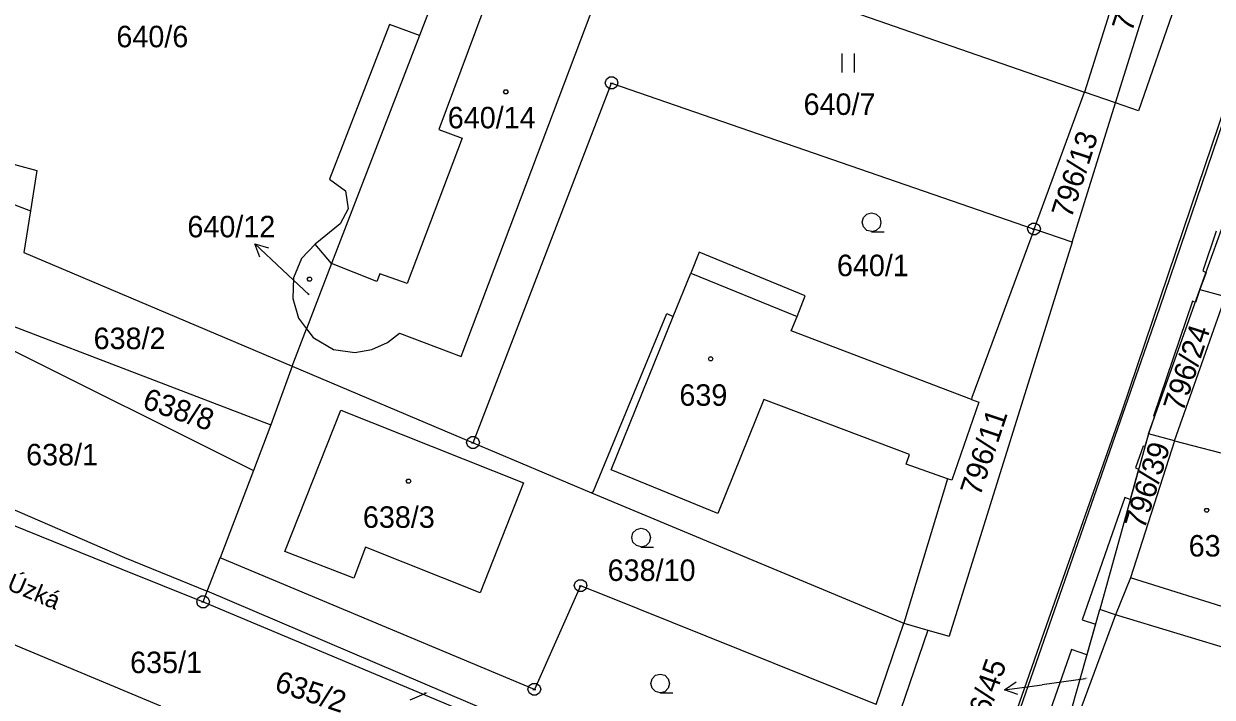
# Model space of a CAD drawing. Extents: x -759060 to -757386, y -1172273 to -1170948.
# Drawn here: x -758101.6 to -758007.6, y -1171349.3 to -1171296.1 of the extents above; entities that cross this region are included whole.
import ezdxf

# ---------------------------------------------------------------- set-up
doc = ezdxf.new("R2010")
doc.units = 0
for name, color, linetype in [('Vrstva 1', 7, 'Continuous'), ('Vrstva 12', 7, 'Continuous'), ('Vrstva 13', 7, 'Continuous'), ('Vrstva 2', 7, 'Continuous'), ('Vrstva 3', 7, 'Continuous'), ('Vrstva 4', 7, 'Continuous'), ('Vrstva 5', 7, 'Continuous'), ('Vrstva 7', 7, 'Continuous'), ('Vrstva 8', 7, 'Continuous')]:
    doc.layers.add(name, color=color, linetype=linetype)

msp = doc.modelspace()

# ---------------------------------------------------------------- linework, layer by layer
at = {"layer": 'Vrstva 1'}
for p, q in [((-758015.23, -1171302.33), (-758009.67, -1171284.51)), ((-758053.7, -1171288.99), (-758017.68, -1171301.49)), ((-758068.26, -1171291.73), (-758070.29, -1171297.01)), ((-758066.98, -1171322.4), (-758055.84, -1171292.86)), ((-758015.58, -1171294.8), (-758017.68, -1171301.49)), ((-758010.54, -1171294.68), (-758013.41, -1171302.97)), ((-758072.67, -1171296.15), (-758077.4, -1171308.38)), ((-758070.29, -1171297.01), (-758072.67, -1171296.15)), ((-758070.29, -1171297.01), (-758077.24, -1171315.05)), ((-758005.04, -1171298.81), (-758011.77, -1171318.56)), ((-758066.05, -1171329.21), (-758055.09, -1171300.77)), ((-758055.09, -1171300.77), (-758021.68, -1171312.32)), ((-758021.68, -1171312.32), (-758017.68, -1171301.49)), ((-758015.23, -1171302.33), (-758017.68, -1171301.49)), ((-758018.67, -1171313.36), (-758015.23, -1171302.33)), ((-758013.41, -1171302.97), (-758015.23, -1171302.33)), ((-758115.76, -1171303.61), (-758100.54, -1171307.69)), ((-758118.62, -1171304.17), (-758101.05, -1171310.87)), ((-758100.54, -1171307.69), (-758101.05, -1171310.87)), ((-758077.4, -1171308.38), (-758076.15, -1171309.28)), ((-758076.15, -1171309.28), (-758075.92, -1171310.72)), ((-758008.56, -1171317.1), (-758006.18, -1171310.44)), ((-758101.05, -1171310.87), (-758101.57, -1171314.17)), ((-758075.92, -1171310.72), (-758076.56, -1171311.89)), ((-758076.56, -1171311.89), (-758078.53, -1171313.5)), ((-758021.68, -1171312.32), (-758026.59, -1171325.64)), ((-758018.67, -1171313.36), (-758021.68, -1171312.32)), ((-758101.57, -1171314.17), (-758080.36, -1171323.15)), ((-758078.53, -1171313.5), (-758079.63, -1171314.63)), ((-758048.16, -1171314.15), (-758048.82, -1171315.79)), ((-758039.77, -1171317.6), (-758048.16, -1171314.15)), ((-758018.67, -1171313.36), (-758028.39, -1171344.5)), ((-758079.63, -1171314.63), (-758080.25, -1171316.18)), ((-758077.24, -1171315.05), (-758079.22, -1171320.2)), ((-758050.21, -1171319.22), (-758048.82, -1171315.79)), ((-758080.25, -1171316.18), (-758080.3, -1171317.81)), ((-758080.3, -1171317.81), (-758079.86, -1171319.36)), ((-758040.42, -1171319.22), (-758039.77, -1171317.6)), ((-758012.64, -1171328.52), (-758008.56, -1171317.1)), ((-758010.57, -1171329.06), (-758006.53, -1171317.65)), ((-758008.56, -1171317.1), (-758006.53, -1171317.65)), ((-758011.77, -1171318.56), (-758028.48, -1171366.58)), ((-758102.97, -1171319.79), (-758082.04, -1171327.79)), ((-758079.86, -1171319.36), (-758079.22, -1171320.2)), ((-758056.53, -1171333.03), (-758050.73, -1171319)), ((-758050.73, -1171319), (-758050.21, -1171319.22)), ((-758040.88, -1171320.35), (-758040.42, -1171319.22)), ((-758080.36, -1171323.15), (-758079.22, -1171320.2)), ((-758079.22, -1171320.2), (-758078.69, -1171320.9)), ((-758072.83, -1171321.29), (-758071.87, -1171320.56)), ((-758071.87, -1171320.56), (-758066.98, -1171322.4)), ((-758026.63, -1171325.78), (-758040.88, -1171320.35)), ((-758103.62, -1171321.33), (-758083.42, -1171331.4)), ((-758078.69, -1171320.9), (-758077.08, -1171321.83)), ((-758074.05, -1171321.85), (-758072.83, -1171321.29)), ((-758077.08, -1171321.83), (-758075.4, -1171322.08)), ((-758075.4, -1171322.08), (-758074.05, -1171321.85)), ((-758080.36, -1171323.15), (-758082.04, -1171327.79)), ((-758080.36, -1171323.15), (-758066.05, -1171329.21)), ((-758124.28, -1171325.01), (-758093.63, -1171338.29)), ((-758026.05, -1171326), (-758028.18, -1171332.18)), ((-758026.59, -1171325.64), (-758026.63, -1171325.78)), ((-758026.63, -1171325.78), (-758026.05, -1171326)), ((-758123.07, -1171327.4), (-758093.82, -1171339.21)), ((-758080.93, -1171337.82), (-758076.5, -1171326.63)), ((-758076.5, -1171326.63), (-758062.06, -1171332.38)), ((-758082.04, -1171327.79), (-758083.42, -1171331.4)), ((-758066.05, -1171329.21), (-758056.67, -1171333.18)), ((-758012.64, -1171328.52), (-758016.49, -1171342.4)), ((-758010.57, -1171329.06), (-758014.04, -1171339.89)), ((-758010.57, -1171329.06), (-758012.64, -1171328.52)), ((-758010.57, -1171329.06), (-758000.35, -1171331.74)), ((-758083.42, -1171331.4), (-758086.06, -1171338.31)), ((-758028.53, -1171332.06), (-758031.98, -1171343.48)), ((-758028.18, -1171332.18), (-758028.53, -1171332.06)), ((-758062.06, -1171332.38), (-758065.5, -1171341.07)), ((-758056.67, -1171333.18), (-758056.53, -1171333.03)), ((-758056.67, -1171333.18), (-758031.98, -1171343.48)), ((-758090.74, -1171350.03), (-758125.45, -1171335.56)), ((-758074.57, -1171337.47), (-758075.48, -1171339.92)), ((-758065.5, -1171341.07), (-758074.57, -1171337.47)), ((-758093.63, -1171338.29), (-758087.08, -1171340.96)), ((-758087.08, -1171340.96), (-758086.06, -1171338.31)), ((-758061.2, -1171348.72), (-758086.06, -1171338.31)), ((-758075.48, -1171339.92), (-758080.93, -1171337.82)), ((-758093.82, -1171339.21), (-758087.4, -1171341.8)), ((-758057.54, -1171340.52), (-758061.2, -1171348.72)), ((-758055.68, -1171341.27), (-758057.54, -1171340.52)), ((-758014.04, -1171339.89), (-758015.25, -1171342.81)), ((-758087.4, -1171341.8), (-758087.08, -1171340.96)), ((-758062.42, -1171351.45), (-758087.08, -1171340.96)), ((-758034.18, -1171349.9), (-758055.68, -1171341.27)), ((-758087.4, -1171341.8), (-758056.26, -1171354.83)), ((-758020.68, -1171357.21), (-758016.49, -1171342.4)), ((-758015.25, -1171342.81), (-758016.49, -1171342.4)), ((-758015.25, -1171342.81), (-758018.53, -1171351.67)), ((-758001.93, -1171346.84), (-758015.25, -1171342.81)), ((-758030.08, -1171344.02), (-758040.94, -1171375.78)), ((-758034.18, -1171349.9), (-758031.98, -1171343.48)), ((-758031.98, -1171343.48), (-758030.08, -1171344.02)), ((-758030.08, -1171344.02), (-758028.39, -1171344.5))]:
    msp.add_line(p, q, dxfattribs=at)
at = {"layer": 'Vrstva 12'}
for p, q in [((-758066.98, -1171322.4), (-758055.84, -1171292.86)), ((-758065.27, -1171295.12), (-758068.76, -1171304.43)), ((-758068.76, -1171304.43), (-758066.91, -1171305.12)), ((-758066.91, -1171305.12), (-758071.27, -1171316.61)), ((-758078.53, -1171313.5), (-758079.63, -1171314.63)), ((-758077.24, -1171315.05), (-758078.53, -1171313.5)), ((-758079.63, -1171314.63), (-758080.25, -1171316.18)), ((-758073.65, -1171316.46), (-758077.24, -1171315.05)), ((-758073.42, -1171315.85), (-758073.65, -1171316.46)), ((-758071.27, -1171316.61), (-758073.42, -1171315.85)), ((-758050.21, -1171319.22), (-758048.82, -1171315.79)), ((-758048.82, -1171315.79), (-758040.42, -1171319.22)), ((-758080.25, -1171316.18), (-758080.3, -1171317.81)), ((-758080.3, -1171317.81), (-758079.86, -1171319.36)), ((-758010.57, -1171329.06), (-758006.53, -1171317.65)), ((-758079.86, -1171319.36), (-758079.22, -1171320.2)), ((-758055.12, -1171331.36), (-758050.21, -1171319.22)), ((-758040.88, -1171320.35), (-758040.42, -1171319.22)), ((-758079.22, -1171320.2), (-758078.69, -1171320.9)), ((-758072.83, -1171321.29), (-758071.87, -1171320.56)), ((-758071.87, -1171320.56), (-758066.98, -1171322.4)), ((-758026.63, -1171325.78), (-758040.88, -1171320.35)), ((-758078.69, -1171320.9), (-758077.08, -1171321.83)), ((-758074.05, -1171321.85), (-758072.83, -1171321.29)), ((-758077.08, -1171321.83), (-758075.4, -1171322.08)), ((-758075.4, -1171322.08), (-758074.05, -1171321.85)), ((-758043.06, -1171325.78), (-758046.69, -1171334.8)), ((-758031.53, -1171330.15), (-758043.06, -1171325.78)), ((-758026.05, -1171326), (-758028.18, -1171332.18)), ((-758026.63, -1171325.78), (-758026.05, -1171326)), ((-758080.93, -1171337.82), (-758076.5, -1171326.63)), ((-758076.5, -1171326.63), (-758062.06, -1171332.38)), ((-758010.57, -1171329.06), (-758014.04, -1171339.89)), ((-758010.57, -1171329.06), (-758000.35, -1171331.74)), ((-758010.57, -1171329.06), (-758000.35, -1171331.74)), ((-758031.8, -1171330.91), (-758031.53, -1171330.15)), ((-758028.53, -1171332.06), (-758031.8, -1171330.91)), ((-758046.69, -1171334.8), (-758055.12, -1171331.36)), ((-758028.18, -1171332.18), (-758028.53, -1171332.06)), ((-758062.06, -1171332.38), (-758065.5, -1171341.07)), ((-758074.57, -1171337.47), (-758075.48, -1171339.92)), ((-758065.5, -1171341.07), (-758074.57, -1171337.47)), ((-758075.48, -1171339.92), (-758080.93, -1171337.82)), ((-758005.32, -1171342.63), (-758014.04, -1171339.89))]:
    msp.add_line(p, q, dxfattribs=at)
at = {"layer": 'Vrstva 13'}
for p, q in [((-758009.23, -1171310.47), (-758005.04, -1171298.09)), ((-758011.08, -1171315.93), (-758009.23, -1171310.47)), ((-758007.27, -1171312.47), (-758008.34, -1171315.63)), ((-758014.75, -1171326.77), (-758011.08, -1171315.93)), ((-758008.07, -1171315.74), (-758008.56, -1171317.1)), ((-758008.34, -1171315.63), (-758008.07, -1171315.74)), ((-758009.15, -1171318.01), (-758012.23, -1171327.12)), ((-758008.92, -1171318.11), (-758009.15, -1171318.01)), ((-758008.56, -1171317.1), (-758008.92, -1171318.11)), ((-758020.66, -1171343.58), (-758014.75, -1171326.77)), ((-758012.15, -1171327.15), (-758012.64, -1171328.52)), ((-758012.23, -1171327.12), (-758012.15, -1171327.15)), ((-758012.64, -1171328.52), (-758012.92, -1171329.52)), ((-758013.05, -1171329.48), (-758013.66, -1171331.19)), ((-758012.92, -1171329.52), (-758013.05, -1171329.48)), ((-758013.41, -1171331.29), (-758014.08, -1171333.71)), ((-758013.66, -1171331.19), (-758013.41, -1171331.29)), ((-758014.49, -1171333.55), (-758017.88, -1171343.21)), ((-758014.08, -1171333.71), (-758014.49, -1171333.55)), ((-758017.88, -1171343.21), (-758016.82, -1171343.57)), ((-758026.92, -1171361.39), (-758020.66, -1171343.58)), ((-758016.82, -1171343.57), (-758017.5, -1171345.98)), ((-758018.71, -1171345.57), (-758024.12, -1171360.96)), ((-758017.5, -1171345.98), (-758018.71, -1171345.57))]:
    msp.add_line(p, q, dxfattribs=at)
at = {"layer": 'Vrstva 3'}
for p, q in [((-758036.88, -1171298.43), (-758036.88, -1171299.93)), ((-758035.88, -1171299.93), (-758035.88, -1171298.43))]:
    msp.add_line(p, q, dxfattribs=at)
for points in [[(-758034.52, -1171312.52), (-758034.9, -1171312.42), (-758035.17, -1171312.15), (-758035.27, -1171311.78), (-758035.17, -1171311.41), (-758034.9, -1171311.14), (-758034.53, -1171311.04), (-758034.16, -1171311.14), (-758033.89, -1171311.41), (-758033.79, -1171311.79), (-758033.89, -1171312.17), (-758034.16, -1171312.44), (-758034.54, -1171312.54), (-758033.54, -1171312.54)], [(-758052.75, -1171337.44), (-758053.13, -1171337.34), (-758053.4, -1171337.07), (-758053.5, -1171336.7), (-758053.4, -1171336.33), (-758053.13, -1171336.06), (-758052.76, -1171335.96), (-758052.39, -1171336.06), (-758052.12, -1171336.33), (-758052.02, -1171336.71), (-758052.12, -1171337.09), (-758052.39, -1171337.36), (-758052.77, -1171337.46), (-758051.77, -1171337.46)], [(-758051.24, -1171348.98), (-758051.62, -1171348.88), (-758051.89, -1171348.61), (-758051.99, -1171348.24), (-758051.89, -1171347.87), (-758051.62, -1171347.6), (-758051.25, -1171347.5), (-758050.88, -1171347.6), (-758050.61, -1171347.87), (-758050.51, -1171348.25), (-758050.61, -1171348.63), (-758050.88, -1171348.9), (-758051.26, -1171349), (-758050.26, -1171349)]]:
    msp.add_lwpolyline(points, dxfattribs=at)
at = {"layer": 'Vrstva 4'}
for p, q in [((-758065.27, -1171295.12), (-758068.76, -1171304.43)), ((-758068.76, -1171304.43), (-758066.91, -1171305.12)), ((-758066.91, -1171305.12), (-758071.27, -1171316.61)), ((-758077.24, -1171315.05), (-758078.53, -1171313.5)), ((-758073.65, -1171316.46), (-758077.24, -1171315.05)), ((-758073.42, -1171315.85), (-758073.65, -1171316.46)), ((-758071.27, -1171316.61), (-758073.42, -1171315.85)), ((-758048.82, -1171315.79), (-758040.42, -1171319.22)), ((-758055.12, -1171331.36), (-758050.21, -1171319.22)), ((-758043.06, -1171325.78), (-758046.69, -1171334.8)), ((-758031.53, -1171330.15), (-758043.06, -1171325.78)), ((-758031.8, -1171330.91), (-758031.53, -1171330.15)), ((-758028.53, -1171332.06), (-758031.8, -1171330.91)), ((-758046.69, -1171334.8), (-758055.12, -1171331.36)), ((-758005.32, -1171342.63), (-758014.04, -1171339.89))]:
    msp.add_line(p, q, dxfattribs=at)
at = {"layer": 'Vrstva 5'}
for points in [[(-758063.37, -1171301.31), (-758063.28, -1171301.46), (-758063.37, -1171301.61), (-758063.55, -1171301.61), (-758063.64, -1171301.46), (-758063.55, -1171301.31)], [(-758078.89, -1171316.13), (-758078.8, -1171316.28), (-758078.89, -1171316.43), (-758079.07, -1171316.43), (-758079.16, -1171316.28), (-758079.07, -1171316.13)], [(-758047.17, -1171322.43), (-758047.08, -1171322.58), (-758047.17, -1171322.73), (-758047.35, -1171322.73), (-758047.44, -1171322.58), (-758047.35, -1171322.43)], [(-758071.06, -1171332.1), (-758070.97, -1171332.25), (-758071.06, -1171332.4), (-758071.24, -1171332.4), (-758071.33, -1171332.25), (-758071.24, -1171332.1)], [(-758007.94, -1171334.4), (-758007.85, -1171334.55), (-758007.94, -1171334.7), (-758008.12, -1171334.7), (-758008.21, -1171334.55), (-758008.12, -1171334.4)]]:
    msp.add_lwpolyline(points, close=True, dxfattribs=at)
at = {"layer": 'Vrstva 7'}
for p, q in [((-758083.303, -1171313.483), (-758081.11, -1171315.53)), ((-758079, -1171317.51), (-758081.11, -1171315.53)), ((-758017.6, -1171347.88), (-758021.04, -1171348.35)), ((-758069.76, -1171349.01), (-758071.06, -1171349.56)), ((-758024.012, -1171348.76), (-758021.04, -1171348.35))]:
    msp.add_line(p, q, dxfattribs=at)
for points in [[(-758082.913, -1171314.531), (-758083.303, -1171313.483), (-758082.231, -1171313.8)], [(-758022.953, -1171349.119), (-758024.012, -1171348.76), (-758023.09, -1171348.128)]]:
    msp.add_lwpolyline(points, dxfattribs=at)
at = {"layer": 'Vrstva 8'}
for p, q in [((-758055.21, -1171300.77), (-758054.97, -1171300.77)), ((-758021.8, -1171312.32), (-758021.56, -1171312.32)), ((-758066.17, -1171329.21), (-758065.93, -1171329.21)), ((-758057.66, -1171340.52), (-758057.42, -1171340.52)), ((-758087.52, -1171341.8), (-758087.28, -1171341.8)), ((-758061.32, -1171348.72), (-758061.08, -1171348.72))]:
    msp.add_line(p, q, dxfattribs=at)
for points in [[(-758054.94, -1171300.29), (-758054.69, -1171300.47), (-758054.59, -1171300.76), (-758054.69, -1171301.05), (-758054.94, -1171301.23), (-758055.25, -1171301.23), (-758055.5, -1171301.05), (-758055.6, -1171300.76), (-758055.5, -1171300.47), (-758055.25, -1171300.29)], [(-758021.53, -1171311.84), (-758021.28, -1171312.02), (-758021.18, -1171312.31), (-758021.28, -1171312.6), (-758021.53, -1171312.78), (-758021.84, -1171312.78), (-758022.09, -1171312.6), (-758022.19, -1171312.31), (-758022.09, -1171312.02), (-758021.84, -1171311.84)], [(-758065.9, -1171328.73), (-758065.65, -1171328.91), (-758065.55, -1171329.2), (-758065.65, -1171329.49), (-758065.9, -1171329.67), (-758066.21, -1171329.67), (-758066.46, -1171329.49), (-758066.56, -1171329.2), (-758066.46, -1171328.91), (-758066.21, -1171328.73)], [(-758057.39, -1171340.04), (-758057.14, -1171340.22), (-758057.04, -1171340.51), (-758057.14, -1171340.8), (-758057.39, -1171340.98), (-758057.7, -1171340.98), (-758057.95, -1171340.8), (-758058.05, -1171340.51), (-758057.95, -1171340.22), (-758057.7, -1171340.04)], [(-758087.25, -1171341.32), (-758087, -1171341.5), (-758086.9, -1171341.79), (-758087, -1171342.08), (-758087.25, -1171342.26), (-758087.56, -1171342.26), (-758087.81, -1171342.08), (-758087.91, -1171341.79), (-758087.81, -1171341.5), (-758087.56, -1171341.32)], [(-758061.05, -1171348.24), (-758060.8, -1171348.42), (-758060.7, -1171348.71), (-758060.8, -1171349), (-758061.05, -1171349.18), (-758061.36, -1171349.18), (-758061.61, -1171349), (-758061.71, -1171348.71), (-758061.61, -1171348.42), (-758061.36, -1171348.24)]]:
    msp.add_lwpolyline(points, close=True, dxfattribs=at)

# ---------------------------------------------------------------- texts
at = {"layer": 'Vrstva 2'}
for s, rotation, p in [('796/38', 72.19268, (-758013.947, -1171296.804)), ('796/13', 72.07809, (-758018.736, -1171311.546)), ('796/24', 71.79161, (-758009.896, -1171326.854)), ('638/8', 341.13907, (-758092.296, -1171326.457)), ('796/11', 71.44784, (-758025.96, -1171333.516)), ('796/39', 72.76564, (-758012.95, -1171336.133))]:
    msp.add_text(s, height=1.7, rotation=rotation, dxfattribs=at).set_placement(p)
for s, height, p in [('640/6', 1.7, (-758094.26, -1171297.94)), ('640/7', 1.7, (-758039.91, -1171303.29)), ('640/14', 1.7, (-758068.051, -1171304.35)), ('640/1', 1.7, (-758037.272, -1171316.04)), ('640/12', 0.1, (-758079.228, -1171317.51)), ('638/2', 1.7, (-758096.061, -1171321.81)), ('639', 1.7, (-758049.731, -1171326.29)), ('638/1', 1.7, (-758101.399, -1171331)), ('638/3', 1.7, (-758074.764, -1171335.94)), ('63', 1.7, (-758009.452, -1171338.21)), ('638/10', 1.7, (-758055.405, -1171340.14)), ('635/1', 1.7, (-758093.173, -1171347.43)), ('796/45', 0.1, (-758017.843, -1171347.88)), ('635/2', 0.1, (-758069.974, -1171349.01))]:
    msp.add_text(s, height=height, dxfattribs=at).set_placement(p)
at = {"layer": 'Vrstva 7'}
msp.add_text('640/12', height=1.7, dxfattribs=at).set_placement((-758088.645, -1171312.97))
for s, height, rotation, p in [('Úzká', 1.4, 337.24296, (-758103.001, -1171340.788)), ('796/45', 1.7, 71.04677, (-758026.091, -1171353.255)), ('635/2', 1.7, 341.76933, (-758081.844, -1171348.812))]:
    msp.add_text(s, height=height, rotation=rotation, dxfattribs=at).set_placement(p)

doc.saveas('drawing.dxf')
